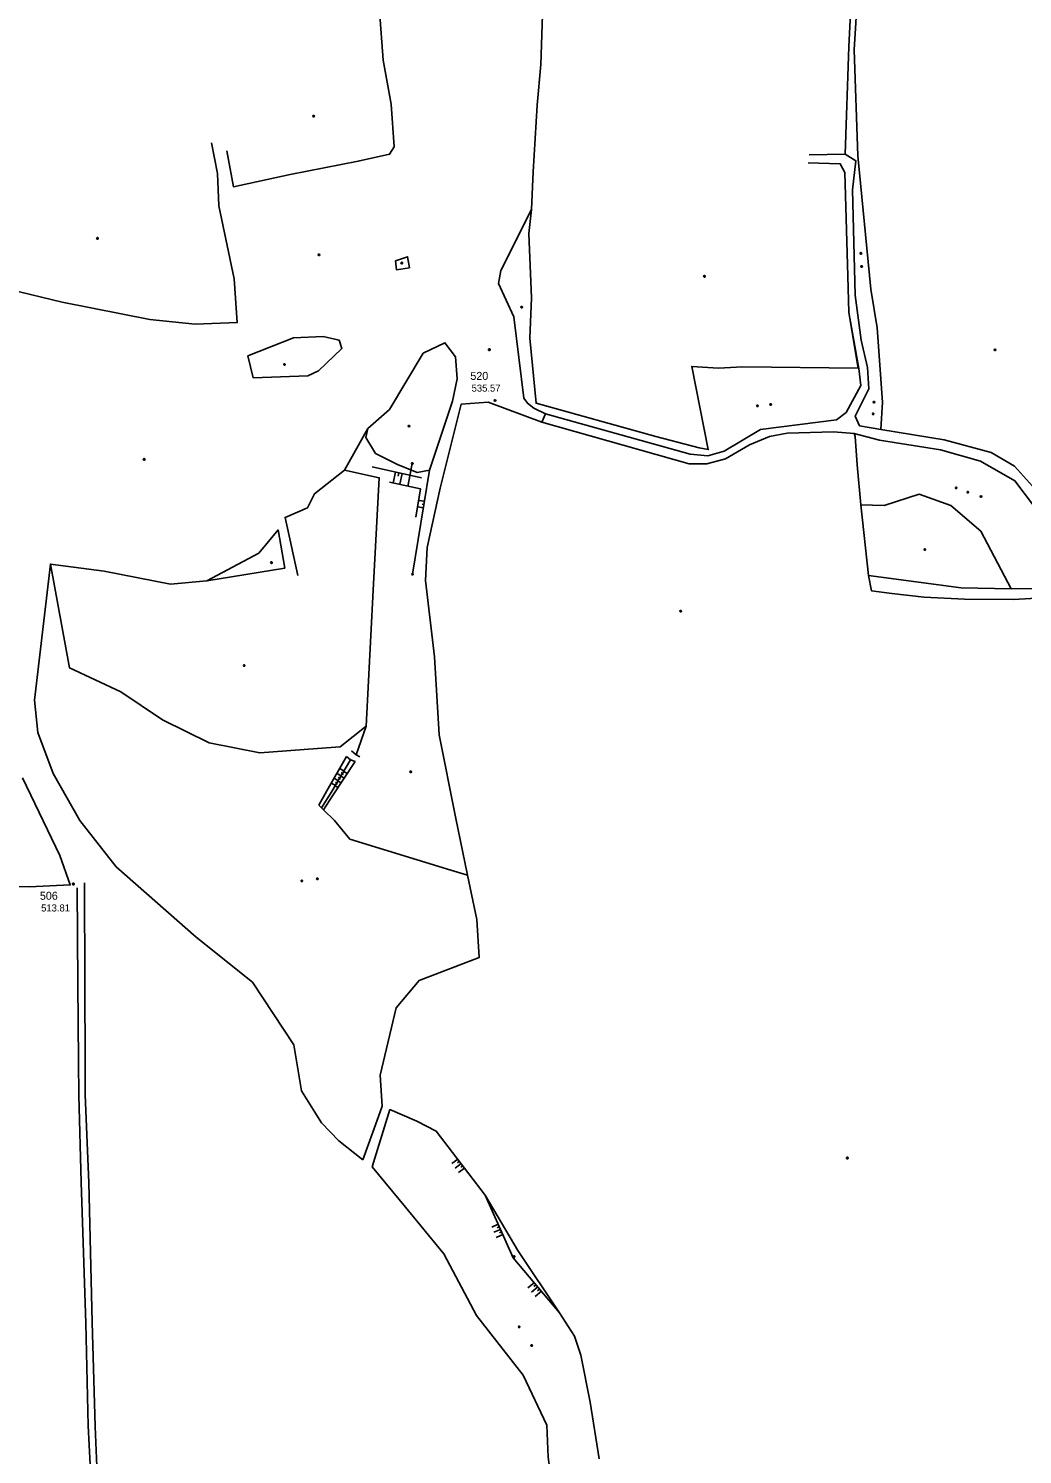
# Model space of a CAD drawing. Extents: x -664960 to -662754, y -993849 to -991145.
# Drawn here: x -664575 to -664152, y -992665 to -992059 of the extents above; entities that cross this region are included whole.
import ezdxf

# ---------------------------------------------------------------- set-up
doc = ezdxf.new("R2010")
doc.units = 0
for name, color, linetype in [('Vrstva 1', 7, 'Continuous'), ('Vrstva 13', 7, 'Continuous'), ('Vrstva 27', 7, 'Continuous'), ('Vrstva 28', 7, 'Continuous'), ('Vrstva 44', 7, 'Continuous'), ('Vrstva 63', 7, 'Continuous'), ('Vrstva 8', 7, 'Continuous')]:
    doc.layers.add(name, color=color, linetype=linetype)

msp = doc.modelspace()

# ---------------------------------------------------------------- linework, layer by layer
at = {"layer": 'Vrstva 13'}
for points in [[(-664453.392, -992096.275), (-664453.212, -992096.575), (-664453.392, -992096.875), (-664453.752, -992096.875), (-664453.932, -992096.575), (-664453.752, -992096.275), (-664453.392, -992096.275)], [(-664545.188, -992148.235), (-664545.008, -992148.535), (-664545.188, -992148.835), (-664545.548, -992148.835), (-664545.728, -992148.535), (-664545.548, -992148.235), (-664545.188, -992148.235)], [(-664451.123, -992155.211), (-664450.943, -992155.511), (-664451.123, -992155.811), (-664451.483, -992155.811), (-664451.663, -992155.511), (-664451.483, -992155.211), (-664451.123, -992155.211)], [(-664220.936, -992154.607), (-664220.756, -992154.907), (-664220.936, -992155.207), (-664221.296, -992155.207), (-664221.476, -992154.907), (-664221.296, -992154.607), (-664220.936, -992154.607)], [(-664220.627, -992160.162), (-664220.447, -992160.462), (-664220.627, -992160.762), (-664220.987, -992160.762), (-664221.167, -992160.462), (-664220.987, -992160.162), (-664220.627, -992160.162)], [(-664287.355, -992164.394), (-664287.175, -992164.694), (-664287.355, -992164.994), (-664287.715, -992164.994), (-664287.895, -992164.694), (-664287.715, -992164.394), (-664287.355, -992164.394)], [(-664364.984, -992177.445), (-664364.804, -992177.745), (-664364.984, -992178.045), (-664365.344, -992178.045), (-664365.524, -992177.745), (-664365.344, -992177.445), (-664364.984, -992177.445)], [(-664378.742, -992195.535), (-664378.562, -992195.835), (-664378.742, -992196.135), (-664379.102, -992196.135), (-664379.282, -992195.835), (-664379.102, -992195.535), (-664378.742, -992195.535)], [(-664163.971, -992195.651), (-664163.791, -992195.951), (-664163.971, -992196.251), (-664164.331, -992196.251), (-664164.511, -992195.951), (-664164.331, -992195.651), (-664163.971, -992195.651)], [(-664465.755, -992201.826), (-664465.575, -992202.126), (-664465.755, -992202.426), (-664466.115, -992202.426), (-664466.295, -992202.126), (-664466.115, -992201.826), (-664465.755, -992201.826)], [(-664215.372, -992217.875), (-664215.192, -992218.175), (-664215.372, -992218.475), (-664215.732, -992218.475), (-664215.912, -992218.175), (-664215.732, -992217.875), (-664215.372, -992217.875)], [(-664264.83, -992219.418), (-664264.65, -992219.718), (-664264.83, -992220.018), (-664265.19, -992220.018), (-664265.37, -992219.718), (-664265.19, -992219.418), (-664264.83, -992219.418)], [(-664259.266, -992218.801), (-664259.086, -992219.101), (-664259.266, -992219.401), (-664259.626, -992219.401), (-664259.806, -992219.101), (-664259.626, -992218.801), (-664259.266, -992218.801)], [(-664215.681, -992222.813), (-664215.501, -992223.113), (-664215.681, -992223.413), (-664216.041, -992223.413), (-664216.221, -992223.113), (-664216.041, -992222.813), (-664215.681, -992222.813)], [(-664525.354, -992242.147), (-664525.174, -992242.447), (-664525.354, -992242.747), (-664525.714, -992242.747), (-664525.894, -992242.447), (-664525.714, -992242.147), (-664525.354, -992242.147)], [(-664180.442, -992254.293), (-664180.262, -992254.593), (-664180.442, -992254.893), (-664180.802, -992254.893), (-664180.982, -992254.593), (-664180.802, -992254.293), (-664180.442, -992254.293)], [(-664175.496, -992256.145), (-664175.316, -992256.445), (-664175.496, -992256.745), (-664175.856, -992256.745), (-664176.036, -992256.445), (-664175.856, -992256.145), (-664175.496, -992256.145)], [(-664169.932, -992257.997), (-664169.752, -992258.297), (-664169.932, -992258.597), (-664170.292, -992258.597), (-664170.472, -992258.297), (-664170.292, -992257.997), (-664169.932, -992257.997)], [(-664193.734, -992280.526), (-664193.554, -992280.826), (-664193.734, -992281.126), (-664194.094, -992281.126), (-664194.274, -992280.826), (-664194.094, -992280.526), (-664193.734, -992280.526)], [(-664471.293, -992286.084), (-664471.113, -992286.384), (-664471.293, -992286.684), (-664471.653, -992286.684), (-664471.833, -992286.384), (-664471.653, -992286.084), (-664471.293, -992286.084)], [(-664297.457, -992306.644), (-664297.277, -992306.944), (-664297.457, -992307.244), (-664297.817, -992307.244), (-664297.997, -992306.944), (-664297.817, -992306.644), (-664297.457, -992306.644)], [(-664482.858, -992329.815), (-664482.678, -992330.115), (-664482.858, -992330.415), (-664483.218, -992330.415), (-664483.398, -992330.115), (-664483.218, -992329.815), (-664482.858, -992329.815)], [(-664412.119, -992374.912), (-664411.939, -992375.212), (-664412.119, -992375.512), (-664412.479, -992375.512), (-664412.659, -992375.212), (-664412.479, -992374.912), (-664412.119, -992374.912)], [(-664458.376, -992421.318), (-664458.196, -992421.618), (-664458.376, -992421.918), (-664458.736, -992421.918), (-664458.916, -992421.618), (-664458.736, -992421.318), (-664458.376, -992421.318)], [(-664451.785, -992420.378), (-664451.605, -992420.678), (-664451.785, -992420.978), (-664452.145, -992420.978), (-664452.325, -992420.678), (-664452.145, -992420.378), (-664451.785, -992420.378)], [(-664226.695, -992539.05), (-664226.515, -992539.35), (-664226.695, -992539.65), (-664227.055, -992539.65), (-664227.235, -992539.35), (-664227.055, -992539.05), (-664226.695, -992539.05)], [(-664368.223, -992580.917), (-664368.043, -992581.217), (-664368.223, -992581.517), (-664368.583, -992581.517), (-664368.763, -992581.217), (-664368.583, -992580.917), (-664368.223, -992580.917)], [(-664366.061, -992610.869), (-664365.881, -992611.169), (-664366.061, -992611.469), (-664366.421, -992611.469), (-664366.601, -992611.169), (-664366.421, -992610.869), (-664366.061, -992610.869)], [(-664360.786, -992618.781), (-664360.606, -992619.081), (-664360.786, -992619.381), (-664361.146, -992619.381), (-664361.326, -992619.081), (-664361.146, -992618.781), (-664360.786, -992618.781)]]:
    msp.add_lwpolyline(points, dxfattribs=at)
at = {"layer": 'Vrstva 27'}
for points in [[(-664117.5, -992291.62), (-664117.31, -992295.87), (-664129.11, -992295.54), (-664133.87, -992288.61), (-664137.02, -992278.21), (-664141.86, -992264.91), (-664146.92, -992255.28), (-664155.82, -992245.31), (-664165.78, -992239.53), (-664185.71, -992234.12), (-664212.61, -992229.72), (-664221.65, -992228.24), (-664223.59, -992224.12), (-664217.7, -992212.51), (-664218.34, -992203.48), (-664220.98, -992191.76), (-664223.6, -992172.7), (-664224.71, -992127.96), (-664223.31, -992115.6), (-664227.78, -992112.81), (-664243.09, -992113.03)], [(-664243.54, -992116.48), (-664229.85, -992116.82), (-664227.94, -992120.61), (-664226.64, -992164.67), (-664226.16, -992180.11), (-664221.99, -992203.84), (-664221.09, -992211.11), (-664227.34, -992222.54), (-664231.51, -992225.69), (-664263.68, -992229.73), (-664279.17, -992239.03), (-664286.12, -992240.97), (-664293.62, -992240.26), (-664355.11, -992223.06), (-664356.61, -992226.61), (-664294.08, -992244.34), (-664286.53, -992244.42), (-664278.54, -992242.31), (-664268.46, -992236.29), (-664259.93, -992232.78), (-664252.47, -992231.4), (-664232.67, -992230.79), (-664224.02, -992231.42), (-664213.22, -992234.29)], [(-664138.52, -992297.4), (-664140.75, -992278.72), (-664147.75, -992262.05), (-664155.69, -992251.52), (-664170.33, -992243.26), (-664187.34, -992238.46), (-664213.22, -992234.29)], [(-664119, -992308.2), (-664120.11, -992304.84), (-664124.67, -992301.76), (-664136.54, -992300.89), (-664156.33, -992302.08), (-664177.07, -992301.85), (-664194.27, -992300.97), (-664207.93, -992299.41), (-664216.54, -992298.34), (-664217.9, -992291.83), (-664178.56, -992297.06), (-664157.27, -992297.5), (-664138.52, -992297.4)], [(-664545.38, -992677.24), (-664546.38, -992653.52), (-664547.68, -992609.19), (-664549.07, -992549.83), (-664550.61, -992512.51), (-664550.62, -992499.03), (-664550.77, -992465.22), (-664550.94, -992422.39)], [(-664554.01, -992424.52), (-664553.65, -992465.27), (-664553.42, -992498.39), (-664553.34, -992512.77), (-664552.22, -992549.66), (-664550.36, -992609.55), (-664549.26, -992653.21), (-664548.03, -992677.85)]]:
    msp.add_lwpolyline(points, dxfattribs=at)
at = {"layer": 'Vrstva 28'}
for points in [[(-664412.883, -992228.019), (-664412.703, -992228.319), (-664412.883, -992228.619), (-664413.243, -992228.619), (-664413.423, -992228.319), (-664413.243, -992228.019), (-664412.883, -992228.019)], [(-664411.47, -992243.9), (-664411.29, -992244.2), (-664411.47, -992244.5), (-664411.83, -992244.5), (-664412.01, -992244.2), (-664411.83, -992243.9), (-664411.47, -992243.9)]]:
    msp.add_lwpolyline(points, dxfattribs=at)
at = {"layer": 'Vrstva 44'}
msp.add_line((-664411.65, -992244.2), (-664413.52, -992253.93), dxfattribs=at)
at = {"layer": 'Vrstva 63'}
for p, q in [((-664494.44, -992121.04), (-664496.9, -992107.95)), ((-664407.76, -992250.27), (-664428.71, -992245.69)), ((-664418.71, -992247.876), (-664419.712, -992252.463)), ((-664417.342, -992248.175), (-664417.643, -992249.551)), ((-664411.54, -992291.3), (-664404.31, -992247.04)), ((-664415.974, -992248.474), (-664416.976, -992253.056)), ((-664406.473, -992260.281), (-664408.944, -992259.878)), ((-664406.924, -992263.045), (-664409.384, -992262.643)), ((-664406.699, -992261.663), (-664407.438, -992261.542)), ((-664221.06, -992261.85), (-664217.9, -992291.83)), ((-664431.273, -992355.825), (-664435.514, -992367.966)), ((-664447.892, -992383.385), (-664439.609, -992368.698)), ((-664435.978, -992370.888), (-664445.484, -992385.488)), ((-664440.669, -992374.884), (-664442.491, -992373.809)), ((-664441.279, -992375.917), (-664441.879, -992375.563)), ((-664440.772, -992375.059), (-664439.271, -992375.945)), ((-664444.329, -992381.085), (-664446.029, -992380.081)), ((-664443.109, -992379.018), (-664444.85, -992377.99)), ((-664444.432, -992381.259), (-664443.203, -992381.985)), ((-664443.719, -992380.051), (-664444.292, -992379.713)), ((-664443.822, -992380.226), (-664443.398, -992380.476)), ((-664441.889, -992376.951), (-664443.67, -992375.9)), ((-664443.212, -992379.192), (-664441.892, -992379.971)), ((-664442.499, -992377.984), (-664443.085, -992377.638)), ((-664442.602, -992378.159), (-664442.148, -992378.427)), ((-664441.992, -992377.126), (-664440.581, -992377.958)), ((-664441.382, -992376.092), (-664440.897, -992376.378)), ((-664447.892, -992383.385), (-664451.331, -992389.482)), ((-664445.484, -992385.488), (-664449.347, -992391.421)), ((-664395.297, -992416.977), (-664388.204, -992419.155)), ((-664421.157, -992518.716), (-664428.731, -992543.13)), ((-664426.052, -992521.746), (-664424.38, -992517.3)), ((-664426.052, -992521.746), (-664432.636, -992540.075)), ((-664422.785, -992523.963), (-664422.785, -992523.963)), ((-664422.785, -992523.963), (-664422.785, -992523.963)), ((-664392.369, -992539.821), (-664394.911, -992541.762)), ((-664390.912, -992541.728), (-664393.455, -992543.671)), ((-664391.641, -992540.774), (-664392.487, -992541.421)), ((-664389.455, -992543.635), (-664392, -992545.579)), ((-664390.184, -992542.682), (-664391.031, -992543.329)), ((-664375.177, -992567.521), (-664377.862, -992568.714)), ((-664374.69, -992568.617), (-664375.594, -992569.019)), ((-664374.202, -992569.714), (-664376.948, -992570.934)), ((-664373.228, -992571.907), (-664376.034, -992573.154)), ((-664373.715, -992570.811), (-664374.64, -992571.221)), ((-664359.897, -992592.346), (-664362.533, -992594.573)), ((-664359.123, -992593.263), (-664360, -992594.004)), ((-664358.348, -992594.18), (-664360.982, -992596.405)), ((-664356.799, -992596.013), (-664359.432, -992598.237)), ((-664357.574, -992595.096), (-664358.451, -992595.837))]:
    msp.add_line(p, q, dxfattribs=at)
for points in [[(-664229.67, -991987.66), (-664222.84, -991994.11), (-664224.09, -992024.18), (-664226.23, -992067.16), (-664227.78, -992112.81)], [(-664219.08, -991986.8), (-664221.33, -992024.66), (-664223.9, -992068.47), (-664222.42, -992113.54), (-664216.91, -992170.19), (-664214.21, -992186.59), (-664211.99, -992218.21), (-664212.61, -992229.72)], [(-664490.46, -992111.33), (-664487.61, -992126.58), (-664463.51, -992121.41), (-664434.59, -992115.77), (-664421.31, -992112.78), (-664419.29, -992109.65), (-664420.58, -992091.49), (-664424.04, -992072.86), (-664427.17, -992030.77)], [(-664355.9, -992040.69), (-664357.02, -992074.72), (-664358.58, -992091.93), (-664360.29, -992120.22), (-664360.94, -992136.22), (-664374.02, -992162.27), (-664375.06, -992167.8), (-664368.52, -992181.86), (-664364.21, -992216.53), (-664362.73, -992218.59), (-664359.95, -992220.64), (-664355.11, -992223.06)], [(-664605.758, -992152.436), (-664603.44, -992164.79), (-664582.56, -992170.22), (-664560.41, -992175.65), (-664523.07, -992182.99), (-664503.85, -992184.99), (-664486, -992184.34), (-664487.26, -992165.81), (-664493.84, -992134.78), (-664494.44, -992121.04)], [(-664226.16, -992180.11), (-664222.31, -992203.78), (-664271.36, -992203.11), (-664281.56, -992203.71), (-664292.97, -992202.97), (-664285.97, -992238.3), (-664289.8, -992237.58), (-664308.21, -992232.78), (-664359.06, -992218.59), (-664361.77, -992191.02), (-664360.97, -992173.84), (-664362.13, -992146.52), (-664360.94, -992136.22)], [(-664418.72, -992158.1), (-664418.39, -992161.9), (-664412.84, -992161.06), (-664413.62, -992156.34), (-664418.72, -992158.1)], [(-664415.92, -992158.71), (-664415.74, -992159.01), (-664415.92, -992159.31), (-664416.28, -992159.31), (-664416.46, -992159.01), (-664416.28, -992158.71), (-664415.92, -992158.71)], [(-664481.46, -992198.49), (-664462.04, -992190.84), (-664449.51, -992190.29), (-664442.65, -992191.86), (-664441.51, -992195.39), (-664451.44, -992204.78), (-664456.03, -992207.01), (-664479.25, -992207.81), (-664481.46, -992198.49)], [(-664404.31, -992247.04), (-664394.61, -992217.75), (-664392.59, -992208.24), (-664393.36, -992198.92), (-664397.77, -992192.94), (-664406.96, -992197.37), (-664421.37, -992221.32), (-664430.52, -992229.42), (-664431.33, -992233.17), (-664427.24, -992239.94), (-664417.86, -992244.65), (-664409.62, -992248.05), (-664404.31, -992247.04)], [(-664424.38, -992517.3), (-664425.31, -992504.14), (-664418.46, -992475.61), (-664408.75, -992463.9), (-664383.19, -992454.15), (-664384.29, -992438.01), (-664388.204, -992419.155), (-664393.34, -992394.41), (-664400.18, -992359.48), (-664402.25, -992326.43), (-664406.04, -992293.95), (-664405.39, -992279.86), (-664399.86, -992254.7), (-664390.84, -992218.94), (-664379.38, -992218.19), (-664356.61, -992226.61)], [(-664430.52, -992229.42), (-664440.48, -992247.08), (-664453.13, -992257.05), (-664456.18, -992263.06), (-664465.66, -992267.14), (-664460.29, -992291.89)], [(-664224.02, -992231.42), (-664223.59, -992232.69), (-664222.73, -992244.85), (-664221.06, -992261.85), (-664211.26, -992262.01), (-664196.38, -992257.3), (-664182.87, -992262.08), (-664170.17, -992272.97), (-664157.27, -992297.5)], [(-664428.3, -992298.11), (-664425.7, -992250.28), (-664440.48, -992247.08)], [(-664421.321, -992252.113), (-664408.164, -992254.969), (-664410.07, -992266.964)], [(-664498.9, -992294.08), (-664476.8, -992282.29), (-664468.67, -992272.47), (-664465.84, -992288.71)], [(-664432.636, -992540.075), (-664442.881, -992532.058), (-664450.25, -992524.45), (-664458.77, -992510.85), (-664461.92, -992491.25), (-664479.56, -992464.64), (-664503.48, -992445.48), (-664537.49, -992415.56), (-664552.89, -992395.96), (-664564.18, -992376.03), (-664570.73, -992358.52), (-664572.15, -992344.73), (-664565.37, -992286.97)], [(-664465.84, -992288.71), (-664498.9, -992294.08), (-664514.29, -992295.47), (-664542.53, -992290.03), (-664565.37, -992286.97), (-664557.27, -992331.03), (-664535.42, -992341.22), (-664517.79, -992353.1), (-664497.88, -992363), (-664476.47, -992367.25), (-664451.91, -992365.33), (-664442.23, -992364.573)], [(-664411.36, -992291), (-664411.18, -992291.3), (-664411.36, -992291.6), (-664411.72, -992291.6), (-664411.9, -992291.3), (-664411.72, -992291), (-664411.36, -992291)], [(-664442.23, -992364.573), (-664431.273, -992355.825), (-664428.3, -992298.11)], [(-664439.609, -992368.698), (-664437.847, -992370.102), (-664435.978, -992370.888)], [(-664437.421, -992366.313), (-664435.514, -992367.966), (-664433.937, -992368.941)], [(-664450.277, -992390.512), (-664446.033, -992383.972), (-664437.847, -992370.102)], [(-664615.3, -992423.09), (-664574.18, -992424.19), (-664556.94, -992423.29), (-664561.39, -992410.84), (-664577.14, -992377.84)], [(-664444.698, -992395.966), (-664449.347, -992391.421), (-664450.277, -992390.512), (-664451.331, -992389.482)], [(-664395.297, -992416.977), (-664438.116, -992403.827), (-664444.698, -992395.966)], [(-664332.26, -992667.23), (-664336.08, -992643.08), (-664340.05, -992623.19), (-664342.81, -992615.08), (-664349.12, -992605.1), (-664366.87, -992578.61), (-664380.69, -992555.11), (-664401.46, -992527.92), (-664409.66, -992523.77), (-664421.157, -992518.716)], [(-664238.165, -992825.482), (-664241.18, -992814.387), (-664247.525, -992801.556), (-664269.052, -992784.463), (-664295.369, -992770.506), (-664314.963, -992759.334), (-664327.184, -992747.594), (-664336.348, -992735.777), (-664344.053, -992717.198), (-664347.494, -992705.3), (-664351.121, -992687.375), (-664353.927, -992666.5), (-664354.473, -992652.836), (-664364.573, -992631.694), (-664384.434, -992606.237), (-664398.285, -992580.153), (-664414.511, -992560.287), (-664428.731, -992543.13)], [(-664380.69, -992555.11), (-664368.86, -992581.74), (-664349.12, -992605.1)]]:
    msp.add_lwpolyline(points, dxfattribs=at)
at = {"layer": 'Vrstva 8'}
for points in [[(-664376.31, -992217.14), (-664376.13, -992217.44), (-664376.31, -992217.74), (-664376.67, -992217.74), (-664376.85, -992217.44), (-664376.67, -992217.14), (-664376.31, -992217.14)], [(-664555.4, -992422.63), (-664555.22, -992422.93), (-664555.4, -992423.23), (-664555.76, -992423.23), (-664555.94, -992422.93), (-664555.76, -992422.63), (-664555.4, -992422.63)]]:
    msp.add_lwpolyline(points, dxfattribs=at)

# ---------------------------------------------------------------- texts
at = {"layer": 'Vrstva 1'}
for s, p in [('520', (-664386.97, -992208.703)), ('506', (-664569.817, -992429.623))]:
    msp.add_text(s, height=3.4, dxfattribs=at).set_placement(p)
at = {"layer": 'Vrstva 63'}
for s, p in [('535.57', (-664386.447, -992213.683)), ('513.81', (-664569.293, -992434.603))]:
    msp.add_text(s, height=3, dxfattribs=at).set_placement(p)

doc.saveas('drawing.dxf')
